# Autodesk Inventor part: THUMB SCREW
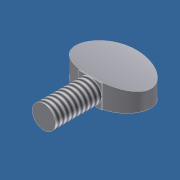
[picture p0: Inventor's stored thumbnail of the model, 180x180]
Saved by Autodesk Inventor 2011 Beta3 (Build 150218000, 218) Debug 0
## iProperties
Shininess: 64.0
Length Units: 11272
Angle Units: 11279
Time Units: 11290
Mass Units: 11286
Length Display Precision: 3
Angle Display Precision: 2
Compacted: True
Part Number: THUMB SCREW
Document SubType Name: Modeling
Created: 2003-11
Designer: Autodesk, Inc.
Manufacturer: Standard
Standards Organization: Custom
Mass: 11.3688 g
Surface Area: 9.71998 cm^2
Volume: 1.44641 cm^3
Density: 7.86 g/cm^3
Material: Steel, Mild
Density: 0.0
Volumn: 0.0
Area: 0.0
PropertySet Name: Model Information
Control State: 0
Master: False
Checked Out: False
Author: Autodesk, Inc.
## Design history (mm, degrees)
sketch "Sketch1"
  geometry: C1 r 3.175 at (0, 0); 1 further point
  constraints: 1 centre point, 1 coincident
  dimensions: "d0" = 6.35 diameter of C1
extrude "Extrusion1" new body sketch "Sketch1" distance "d1" = 12.7; taper "d2" = 0 deg
sketch "Sketch2"
  geometry: L1 (-10.312, 3.175)-(10.312, 3.175); L2 (10.312, 3.175)-(10.312, -3.175); L3 (10.312, -3.175)-(-10.312, -3.175); L4 (-10.312, -3.175)-(-10.312, 3.175); C1 r 3.175 at (0, 0) reference; 1 further point
  constraints: 8 end point, 2 parallel, 1 horizontal, 1 perpendicular
  dimensions: "d3" = 3.175 distance from line of L3 point (0, 0); "d4" = 3.175 distance from line of point (0, 0) L1; "d5" = 20.6248 distance between parallel lines of L2 L4; "d6" = 10.3124 distance from line of L4 point (0, 0) (= 0.5 x d5)
extrude "Extrusion2" join sketch "Sketch2" distance "d7" = 12.7; taper "d8" = 0 deg
sketch "Sketch3"
  geometry: L1 (20.625, 12.7)-(0, 12.7) reference; L2 (0, 0)-(0, 12.7) reference; L3 (10.312, 0)-(0, 0) reference; L4 (20.625, 0)-(10.312, 0) reference; L5 (20.625, 0)-(20.625, 12.7) reference; L6 (10.312, 12.7)-(10.312, 0); L7 (0, 6.35)-(20.625, 6.35); L8 (7.137, 0)-(7.137, -12.7) reference; L9 (13.487, 0)-(13.487, -12.7) reference; L10 (7.137, 0)-(7.137, 0.308); L11 (13.487, 0)-(13.487, 0.308); 1 further point; 1 other entity
  constraints: 8 end point, 4 midpoint, 3 vertical, 1 parallel, 6 other
extrude "Extrusion3" cut sketch "Sketch3" distance "d9" = 12.7; taper "d10" = 0 deg
workplane "Work Plane1"
sketch "Sketch4"
  geometry: L1 (-3.175, -0.308)-(-3.175, -0.308) reference; L2 (3.175, -0.308)-(-3.175, -0.308) reference; L3 (3.175, -0.308)-(3.175, -0.308) reference; L4 (3.175, -0.308)-(-3.175, -0.308) reference; L5 (-3.175, -0.308)-(-3.175, -12.7) reference; L6 (3.175, -12.7)-(3.175, -0.308) reference; L7 (3.175, -12.7)-(3.175, -0.308); L8 (-3.175, -0.308)-(-3.175, -12.7); A1 r 22.382 centre (-24.682, -6.504) between (-3.175, -12.7) and (-3.175, -0.308); A2 r 22.382 centre (24.682, -6.504) between (3.175, -0.308) and (3.175, -12.7)
  constraints: 4 end point, 4 point on circle, 2 centre point, 2 equal length
  dimensions: "d12" = 22.38154 radius of A1; "d13" = 22.38154 radius of A2 (= d12)
extrude "Extrusion4" cut sketch "Sketch4" distance "d14" = 25.4; taper "d15" = 0 deg
thread "Thread1" dims "d16" = 25.4, "d17" = 0
body "Solid1"
node "Projected Loop1"
node "Projected Loop2"
other parameters: "d11" = -12.7
